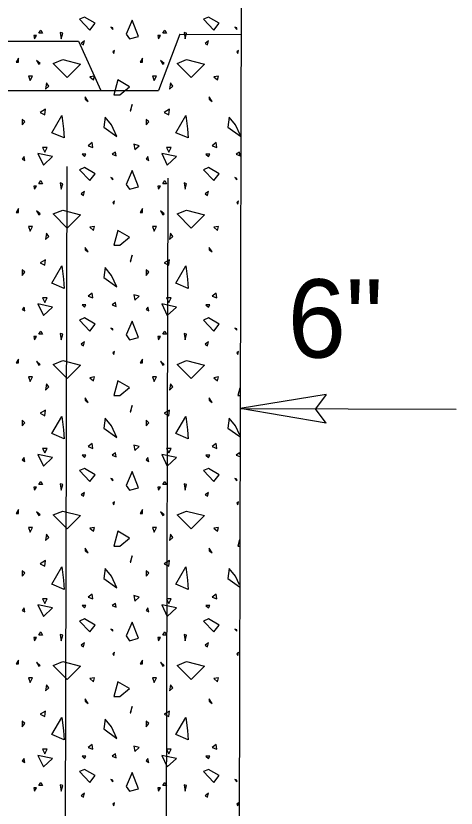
# Model space of a CAD drawing. Extents: x 9.6 to 16.8, y 2.2 to 12.2.
# Drawn here: x 15.979 to 16.317, y 7.596 to 8.202 of the extents above; entities that cross this region are included whole.
import ezdxf

# ---------------------------------------------------------------- set-up
doc = ezdxf.new("R2010")
doc.units = 0
for name, color, linetype in [('DETL-DIMS', 7, 'Continuous'), ('DETL-LINE', 7, 'Continuous'), ('DETL-NOTE', 7, 'Continuous'), ('DETL-PATT', 7, 'Continuous')]:
    doc.layers.add(name, color=color, linetype=linetype)

msp = doc.modelspace()

# ---------------------------------------------------------------- linework, layer by layer
at = {"layer": 'DETL-DIMS'}
for p, q in [((16.21722, 7.91235), (16.15129, 7.90149)), ((16.21722, 7.91235), (16.20894, 7.90137)), ((16.15129, 7.90149), (16.31678, 7.90118)), ((16.21714, 7.89039), (16.15129, 7.90149)), ((16.21714, 7.89039), (16.20894, 7.90137))]:
    msp.add_line(p, q, dxfattribs=at)
at = {"layer": 'DETL-LINE'}
for p, q in [((16.15333, 8.69231), (16.1489, 6.99)), ((14.99573, 8.18549), (16.02733, 8.18278)), ((16.1051, 8.18824), (16.08859, 8.14506)), ((16.1051, 8.18824), (16.15204, 8.18808)), ((16.02733, 8.18278), (16.04459, 8.14518)), ((14.97361, 8.14518), (16.04459, 8.14518)), ((16.04459, 8.14518), (16.08859, 8.14506)), ((16.01859, 8.08698), (16.01596, 7.08408)), ((16.09588, 8.07784), (16.0931, 7.02231))]:
    msp.add_line(p, q, dxfattribs=at)
at = {"layer": 'DETL-PATT'}
for points in [[(16.02827, 8.19961), (16.03604, 8.19129), (16.04027, 8.19651), (16.03192, 8.20133)], [(16.06639, 8.18467), (16.07345, 8.18651), (16.06863, 8.1989), (16.064, 8.18831)], [(16.12329, 8.19961), (16.13106, 8.19129), (16.13529, 8.19651), (16.12694, 8.20133)], [(15.99863, 8.19129), (15.99988, 8.1889), (15.99694, 8.1889)], [(16.0538, 8.19298), (16.05212, 8.19357), (16.0538, 8.19184)], [(16.09365, 8.19129), (16.0949, 8.1889), (16.09192, 8.1889)], [(16.14882, 8.19298), (16.14714, 8.19357), (16.14882, 8.19184)], [(15.99325, 8.18706), (15.9938, 8.18467), (15.9951, 8.18706)], [(16.01345, 8.18945), (16.01416, 8.18467), (16.01529, 8.1889)], [(16.08827, 8.18706), (16.08882, 8.18467), (16.09012, 8.18706)], [(16.10847, 8.18945), (16.10918, 8.18467), (16.11027, 8.1889)], [(16.02953, 8.18114), (16.03122, 8.18), (16.03192, 8.18298)], [(16.12455, 8.18114), (16.12624, 8.18), (16.12694, 8.18298)], [(16.0551, 8.17576), (16.0538, 8.17463), (16.05451, 8.17337)], [(16.15012, 8.17576), (16.14882, 8.17463), (16.14953, 8.17337)], [(15.98141, 8.16984), (15.97969, 8.16686), (15.98141, 8.16686)], [(15.99694, 8.16518), (15.99804, 8.16573), (15.9951, 8.16816)], [(16.01529, 8.16871), (16.02898, 8.16518), (16.01882, 8.15502), (16.00808, 8.16573)], [(16.07639, 8.16984), (16.07471, 8.16686), (16.07639, 8.16686)], [(16.09192, 8.16518), (16.09306, 8.16573), (16.09012, 8.16816)], [(16.11027, 8.16871), (16.124, 8.16518), (16.1138, 8.15502), (16.1031, 8.16573)], [(15.98918, 8.15616), (15.99027, 8.15263), (15.99212, 8.15616)], [(16.03604, 8.15557), (16.03898, 8.15318), (16.03957, 8.15616)], [(16.05918, 8.14188), (16.06639, 8.14796), (16.05749, 8.15318), (16.05451, 8.14188)], [(16.08416, 8.15616), (16.08529, 8.15263), (16.08714, 8.15616)], [(16.13106, 8.15557), (16.134, 8.15318), (16.13459, 8.15616)], [(16.00286, 8.1509), (16.00216, 8.14612), (16.00455, 8.14851)], [(16.09788, 8.1509), (16.09718, 8.14612), (16.09957, 8.14851)], [(16.03251, 8.1402), (16.03251, 8.13835), (16.0349, 8.13667)], [(16.12753, 8.1402), (16.12753, 8.13835), (16.12992, 8.13667)], [(15.99804, 8.12831), (16.00157, 8.12651), (16.00216, 8.13075)], [(16.06694, 8.12945), (16.06753, 8.12945), (16.06863, 8.13427)], [(16.09306, 8.12831), (16.09659, 8.12651), (16.09718, 8.13075)], [(15.98435, 8.12298), (15.98435, 8.11875), (15.9862, 8.12114)], [(16.01584, 8.11576), (16.01639, 8.10871), (16.00694, 8.11278), (16.01471, 8.12592)], [(16.04788, 8.12467), (16.04675, 8.11702), (16.05678, 8.10984), (16.05271, 8.11875)], [(16.07937, 8.12298), (16.07937, 8.11875), (16.08122, 8.12114)], [(16.11086, 8.11576), (16.11141, 8.10871), (16.10196, 8.11278), (16.10973, 8.12592)], [(16.03788, 8.10518), (16.0349, 8.10278), (16.03843, 8.10149)], [(16.13286, 8.10518), (16.12992, 8.10278), (16.13345, 8.10149)], [(15.99988, 8.10149), (16.00157, 8.09796), (16.00341, 8.10149)], [(16.06992, 8.10392), (16.07047, 8.0998), (16.074, 8.10278)], [(16.0949, 8.10149), (16.09659, 8.09796), (16.09843, 8.10149)], [(15.98435, 8.09263), (15.9862, 8.09149), (15.98565, 8.09443)], [(15.99624, 8.09686), (16.00047, 8.08796), (16.00753, 8.09443)], [(16.03012, 8.09627), (16.03192, 8.09443), (16.03306, 8.09627)], [(16.05325, 8.09627), (16.05624, 8.09502), (16.05565, 8.09796)], [(16.07937, 8.09263), (16.08122, 8.09149), (16.08063, 8.09443)], [(16.09122, 8.09686), (16.09545, 8.08796), (16.10251, 8.09443)], [(16.1251, 8.09627), (16.12694, 8.09443), (16.12808, 8.09627)], [(16.14827, 8.09627), (16.15122, 8.09502), (16.15067, 8.09796)], [(16.02827, 8.08443), (16.03604, 8.07608), (16.04027, 8.08133), (16.03192, 8.08612)], [(16.06639, 8.06945), (16.07345, 8.07129), (16.06863, 8.08373), (16.064, 8.07314)], [(16.12329, 8.08443), (16.13106, 8.07608), (16.13529, 8.08133), (16.12694, 8.08612)], [(15.99863, 8.07608), (15.99988, 8.07369), (15.99694, 8.07369)], [(16.01345, 8.07427), (16.01416, 8.06945), (16.01529, 8.07369)], [(16.0538, 8.0778), (16.05212, 8.07835), (16.0538, 8.07667)], [(16.09365, 8.07608), (16.0949, 8.07369), (16.09192, 8.07369)], [(16.10847, 8.07427), (16.10918, 8.06945), (16.11027, 8.07369)], [(16.14882, 8.0778), (16.14714, 8.07835), (16.14882, 8.07667)], [(15.99325, 8.07184), (15.9938, 8.06945), (15.9951, 8.07184)], [(16.08827, 8.07184), (16.08882, 8.06945), (16.09012, 8.07184)], [(16.02953, 8.06592), (16.03122, 8.06478), (16.03192, 8.06776)], [(16.12455, 8.06592), (16.12624, 8.06478), (16.12694, 8.06776)], [(16.0551, 8.06055), (16.0538, 8.05945), (16.05451, 8.05816)], [(16.15012, 8.06055), (16.14882, 8.05945), (16.14953, 8.05816)], [(15.98141, 8.05463), (15.97969, 8.05169), (15.98141, 8.05169)], [(15.99694, 8.04996), (15.99804, 8.05055), (15.9951, 8.05294)], [(16.01529, 8.05349), (16.02898, 8.04996), (16.01882, 8.0398), (16.00808, 8.05055)], [(16.07639, 8.05463), (16.07471, 8.05169), (16.07639, 8.05169)], [(16.09192, 8.04996), (16.09306, 8.05055), (16.09012, 8.05294)], [(16.11027, 8.05349), (16.124, 8.04996), (16.1138, 8.0398), (16.1031, 8.05055)], [(15.98918, 8.04094), (15.99027, 8.03741), (15.99212, 8.04094)], [(16.03604, 8.04039), (16.03898, 8.03796), (16.03957, 8.04094)], [(16.05918, 8.02667), (16.06639, 8.03275), (16.05749, 8.03796), (16.05451, 8.02667)], [(16.08416, 8.04094), (16.08529, 8.03741), (16.08714, 8.04094)], [(16.13106, 8.04039), (16.134, 8.03796), (16.13459, 8.04094)], [(16.00286, 8.03573), (16.00216, 8.0309), (16.00455, 8.03333)], [(16.09788, 8.03573), (16.09718, 8.0309), (16.09957, 8.03333)], [(16.03251, 8.02498), (16.03251, 8.02314), (16.0349, 8.02145)], [(16.12753, 8.02498), (16.12753, 8.02314), (16.12992, 8.02145)], [(15.99804, 8.01314), (16.00157, 8.01129), (16.00216, 8.01553)], [(16.06694, 8.01427), (16.06753, 8.01427), (16.06863, 8.01906)], [(16.09306, 8.01314), (16.09659, 8.01129), (16.09718, 8.01553)], [(15.98435, 8.00776), (15.98435, 8.00353), (15.9862, 8.00592)], [(16.01584, 8.00055), (16.01639, 7.99349), (16.00694, 7.99761), (16.01471, 8.01075)], [(16.04788, 8.00945), (16.04675, 8.00184), (16.05678, 7.99463), (16.05271, 8.00353)], [(16.07937, 8.00776), (16.07937, 8.00353), (16.08122, 8.00592)], [(16.11086, 8.00055), (16.11141, 7.99349), (16.10196, 7.99761), (16.10973, 8.01075)], [(16.03788, 7.98996), (16.0349, 7.98757), (16.03843, 7.98631)], [(16.13286, 7.98996), (16.12992, 7.98757), (16.13345, 7.98631)], [(15.99988, 7.98631), (16.00157, 7.98278), (16.00341, 7.98631)], [(16.06992, 7.98871), (16.07047, 7.98463), (16.074, 7.98757)], [(16.0949, 7.98631), (16.09659, 7.98278), (16.09843, 7.98631)], [(15.98435, 7.97741), (15.9862, 7.97627), (15.98565, 7.97925)], [(15.99624, 7.98165), (16.00047, 7.97275), (16.00753, 7.97925)], [(16.03012, 7.9811), (16.03192, 7.97925), (16.03306, 7.9811)], [(16.05325, 7.9811), (16.05624, 7.9798), (16.05565, 7.98278)], [(16.07937, 7.97741), (16.08122, 7.97627), (16.08063, 7.97925)], [(16.09122, 7.98165), (16.09545, 7.97275), (16.10251, 7.97925)], [(16.1251, 7.9811), (16.12694, 7.97925), (16.12808, 7.9811)], [(16.02827, 7.96922), (16.03604, 7.9609), (16.04027, 7.96612), (16.03192, 7.9709)], [(16.06639, 7.95427), (16.07345, 7.95608), (16.06863, 7.96851), (16.064, 7.95792)], [(16.12329, 7.96922), (16.13106, 7.9609), (16.13529, 7.96612), (16.12694, 7.9709)], [(15.99863, 7.9609), (15.99988, 7.95851), (15.99694, 7.95851)], [(16.01345, 7.95906), (16.01416, 7.95427), (16.01529, 7.95851)], [(16.0538, 7.96259), (16.05212, 7.96314), (16.0538, 7.96145)], [(16.09365, 7.9609), (16.0949, 7.95851), (16.09192, 7.95851)], [(16.10847, 7.95906), (16.10918, 7.95427), (16.11027, 7.95851)], [(16.14882, 7.96259), (16.14714, 7.96314), (16.14882, 7.96145)], [(15.99325, 7.95667), (15.9938, 7.95427), (15.9951, 7.95667)], [(16.08827, 7.95667), (16.08882, 7.95427), (16.09012, 7.95667)], [(16.02953, 7.95075), (16.03122, 7.94961), (16.03192, 7.95255)], [(16.12455, 7.95075), (16.12624, 7.94961), (16.12694, 7.95255)], [(16.0551, 7.94537), (16.0538, 7.94424), (16.05451, 7.94298)], [(16.15012, 7.94537), (16.14882, 7.94424), (16.14953, 7.94298)], [(15.98141, 7.93945), (15.97969, 7.93647), (15.98141, 7.93647)], [(15.99694, 7.93478), (15.99804, 7.93533), (15.9951, 7.93773)], [(16.01529, 7.93831), (16.02898, 7.93478), (16.01882, 7.92463), (16.00808, 7.93533)], [(16.07639, 7.93945), (16.07471, 7.93647), (16.07639, 7.93647)], [(16.09192, 7.93478), (16.09306, 7.93533), (16.09012, 7.93773)], [(16.11027, 7.93831), (16.124, 7.93478), (16.1138, 7.92463), (16.1031, 7.93533)], [(15.98918, 7.92573), (15.99027, 7.9222), (15.99212, 7.92573)], [(16.03604, 7.92518), (16.03898, 7.92278), (16.03957, 7.92573)], [(16.05918, 7.91149), (16.06639, 7.91757), (16.05749, 7.92278), (16.05451, 7.91149)], [(16.08416, 7.92573), (16.08529, 7.9222), (16.08714, 7.92573)], [(16.13106, 7.92518), (16.134, 7.92278), (16.13459, 7.92573)], [(16.00286, 7.92051), (16.00216, 7.91573), (16.00455, 7.91812)], [(16.09788, 7.92051), (16.09718, 7.91573), (16.09957, 7.91812)], [(16.03251, 7.9098), (16.03251, 7.90796), (16.0349, 7.90627)], [(16.12753, 7.9098), (16.12753, 7.90796), (16.12992, 7.90627)], [(15.99804, 7.89792), (16.00157, 7.89608), (16.00216, 7.90031)], [(16.06694, 7.89906), (16.06753, 7.89906), (16.06863, 7.90384)], [(16.09306, 7.89792), (16.09659, 7.89608), (16.09718, 7.90031)], [(15.98435, 7.89255), (15.98435, 7.88831), (15.9862, 7.89075)], [(16.01584, 7.88537), (16.01639, 7.87831), (16.00694, 7.88239), (16.01471, 7.89553)], [(16.04788, 7.89427), (16.04675, 7.88663), (16.05678, 7.87945), (16.05271, 7.88831)], [(16.07937, 7.89255), (16.07937, 7.88831), (16.08122, 7.89075)], [(16.11086, 7.88537), (16.11141, 7.87831), (16.10196, 7.88239), (16.10973, 7.89553)], [(16.03788, 7.87478), (16.0349, 7.87239), (16.03843, 7.8711)], [(16.13286, 7.87478), (16.12992, 7.87239), (16.13345, 7.8711)], [(15.99988, 7.8711), (16.00157, 7.86757), (16.00341, 7.8711)], [(16.06992, 7.87349), (16.07047, 7.86941), (16.074, 7.87239)], [(16.0949, 7.8711), (16.09659, 7.86757), (16.09843, 7.8711)], [(15.98435, 7.8622), (15.9862, 7.8611), (15.98565, 7.86404)], [(15.99624, 7.86643), (16.00047, 7.85757), (16.00753, 7.86404)], [(16.03012, 7.86588), (16.03192, 7.86404), (16.03306, 7.86588)], [(16.05325, 7.86588), (16.05624, 7.86463), (16.05565, 7.86757)], [(16.07937, 7.8622), (16.08122, 7.8611), (16.08063, 7.86404)], [(16.09122, 7.86643), (16.09545, 7.85757), (16.10251, 7.86404)], [(16.1251, 7.86588), (16.12694, 7.86404), (16.12808, 7.86588)], [(16.02827, 7.85404), (16.03604, 7.84569), (16.04027, 7.8509), (16.03192, 7.85573)], [(16.06639, 7.83906), (16.07345, 7.8409), (16.06863, 7.85333), (16.064, 7.84275)], [(16.12329, 7.85404), (16.13106, 7.84569), (16.13529, 7.8509), (16.12694, 7.85573)], [(15.99863, 7.84569), (15.99988, 7.84329), (15.99694, 7.84329)], [(16.01345, 7.84384), (16.01416, 7.83906), (16.01529, 7.84329)], [(16.0538, 7.84737), (16.05212, 7.84796), (16.0538, 7.84627)], [(16.09365, 7.84569), (16.0949, 7.84329), (16.09192, 7.84329)], [(16.10847, 7.84384), (16.10918, 7.83906), (16.11027, 7.84329)], [(16.14882, 7.84737), (16.14714, 7.84796), (16.14882, 7.84627)], [(15.99325, 7.84145), (15.9938, 7.83906), (15.9951, 7.84145)], [(16.08827, 7.84145), (16.08882, 7.83906), (16.09012, 7.84145)], [(16.02953, 7.83553), (16.03122, 7.83439), (16.03192, 7.83737)], [(16.12455, 7.83553), (16.12624, 7.83439), (16.12694, 7.83737)], [(16.0551, 7.83016), (16.0538, 7.82902), (16.05451, 7.82776)], [(16.15012, 7.83016), (16.14882, 7.82902), (16.14953, 7.82776)], [(15.98141, 7.82424), (15.97969, 7.82125), (15.98141, 7.82125)], [(15.99694, 7.81957), (15.99804, 7.82016), (15.9951, 7.82255)], [(16.01529, 7.8231), (16.02898, 7.81957), (16.01882, 7.80941), (16.00808, 7.82016)], [(16.07639, 7.82424), (16.07471, 7.82125), (16.07639, 7.82125)], [(16.09192, 7.81957), (16.09306, 7.82016), (16.09012, 7.82255)], [(16.11027, 7.8231), (16.124, 7.81957), (16.1138, 7.80941), (16.1031, 7.82016)], [(15.98918, 7.81055), (15.99027, 7.80702), (15.99212, 7.81055)], [(16.03604, 7.80996), (16.03898, 7.80757), (16.03957, 7.81055)], [(16.05918, 7.79627), (16.06639, 7.80235), (16.05749, 7.80757), (16.05451, 7.79627)], [(16.08416, 7.81055), (16.08529, 7.80702), (16.08714, 7.81055)], [(16.13106, 7.80996), (16.134, 7.80757), (16.13459, 7.81055)], [(16.00286, 7.80533), (16.00216, 7.80051), (16.00455, 7.8029)], [(16.09788, 7.80533), (16.09718, 7.80051), (16.09957, 7.8029)], [(16.03251, 7.79459), (16.03251, 7.79275), (16.0349, 7.79106)], [(16.12753, 7.79459), (16.12753, 7.79275), (16.12992, 7.79106)], [(15.99804, 7.78275), (16.00157, 7.7809), (16.00216, 7.78514)], [(16.06694, 7.78384), (16.06753, 7.78384), (16.06863, 7.78867)], [(16.09306, 7.78275), (16.09659, 7.7809), (16.09718, 7.78514)], [(15.98435, 7.77737), (15.98435, 7.77314), (15.9862, 7.77553)], [(16.01584, 7.77016), (16.01639, 7.7631), (16.00694, 7.76722), (16.01471, 7.78031)], [(16.04788, 7.77906), (16.04675, 7.77145), (16.05678, 7.76424), (16.05271, 7.77314)], [(16.07937, 7.77737), (16.07937, 7.77314), (16.08122, 7.77553)], [(16.11086, 7.77016), (16.11141, 7.7631), (16.10196, 7.76722), (16.10973, 7.78031)], [(16.03788, 7.75957), (16.0349, 7.75718), (16.03843, 7.75592)], [(16.13286, 7.75957), (16.12992, 7.75718), (16.13345, 7.75592)], [(15.99988, 7.75592), (16.00157, 7.75239), (16.00341, 7.75592)], [(16.06992, 7.75831), (16.07047, 7.7542), (16.074, 7.75718)], [(16.0949, 7.75592), (16.09659, 7.75239), (16.09843, 7.75592)], [(15.98435, 7.74702), (15.9862, 7.74588), (15.98565, 7.74886)], [(15.99624, 7.75125), (16.00047, 7.74235), (16.00753, 7.74886)], [(16.03012, 7.75067), (16.03192, 7.74886), (16.03306, 7.75067)], [(16.05325, 7.75067), (16.05624, 7.74941), (16.05565, 7.75239)], [(16.07937, 7.74702), (16.08122, 7.74588), (16.08063, 7.74886)], [(16.09122, 7.75125), (16.09545, 7.74235), (16.10251, 7.74886)], [(16.1251, 7.75067), (16.12694, 7.74886), (16.12808, 7.75067)], [(16.02827, 7.73882), (16.03604, 7.73051), (16.04027, 7.73573), (16.03192, 7.74051)], [(16.06639, 7.72384), (16.07345, 7.72569), (16.06863, 7.73812), (16.064, 7.72753)], [(16.12329, 7.73882), (16.13106, 7.73051), (16.13529, 7.73573), (16.12694, 7.74051)], [(15.99863, 7.73051), (15.99988, 7.72808), (15.99694, 7.72808)], [(16.01345, 7.72867), (16.01416, 7.72384), (16.01529, 7.72808)], [(16.0538, 7.7322), (16.05212, 7.73275), (16.0538, 7.73106)], [(16.09365, 7.73051), (16.0949, 7.72808), (16.09192, 7.72808)], [(16.10847, 7.72867), (16.10918, 7.72384), (16.11027, 7.72808)], [(16.14882, 7.7322), (16.14714, 7.73275), (16.14882, 7.73106)], [(15.99325, 7.72627), (15.9938, 7.72384), (15.9951, 7.72627)], [(16.08827, 7.72627), (16.08882, 7.72384), (16.09012, 7.72627)], [(16.02953, 7.72031), (16.03122, 7.71922), (16.03192, 7.72216)], [(16.12455, 7.72031), (16.12624, 7.71922), (16.12694, 7.72216)], [(16.0551, 7.71498), (16.0538, 7.71384), (16.05451, 7.71255)], [(16.15012, 7.71498), (16.14882, 7.71384), (16.14953, 7.71255)], [(15.98141, 7.70902), (15.97969, 7.70608), (15.98141, 7.70608)], [(15.99694, 7.70439), (15.99804, 7.70494), (15.9951, 7.70733)], [(16.01529, 7.70792), (16.02898, 7.70439), (16.01882, 7.6942), (16.00808, 7.70494)], [(16.07639, 7.70902), (16.07471, 7.70608), (16.07639, 7.70608)], [(16.09192, 7.70439), (16.09306, 7.70494), (16.09012, 7.70733)], [(16.11027, 7.70792), (16.124, 7.70439), (16.1138, 7.6942), (16.1031, 7.70494)], [(15.98918, 7.69533), (15.99027, 7.6918), (15.99212, 7.69533)], [(16.03604, 7.69478), (16.03898, 7.69239), (16.03957, 7.69533)], [(16.05918, 7.6811), (16.06639, 7.68714), (16.05749, 7.69239), (16.05451, 7.6811)], [(16.08416, 7.69533), (16.08529, 7.6918), (16.08714, 7.69533)], [(16.13106, 7.69478), (16.134, 7.69239), (16.13459, 7.69533)], [(16.00286, 7.69012), (16.00216, 7.68533), (16.00455, 7.68773)], [(16.09788, 7.69012), (16.09718, 7.68533), (16.09957, 7.68773)], [(16.03251, 7.67937), (16.03251, 7.67757), (16.0349, 7.67584)], [(16.12753, 7.67937), (16.12753, 7.67757), (16.12992, 7.67584)], [(15.99804, 7.66753), (16.00157, 7.66569), (16.00216, 7.66992)], [(16.06694, 7.66867), (16.06753, 7.66867), (16.06863, 7.67345)], [(16.09306, 7.66753), (16.09659, 7.66569), (16.09718, 7.66992)], [(15.98435, 7.66216), (15.98435, 7.65792), (15.9862, 7.66031)], [(16.01584, 7.65498), (16.01639, 7.64792), (16.00694, 7.652), (16.01471, 7.66514)], [(16.04788, 7.66384), (16.04675, 7.65624), (16.05678, 7.64902), (16.05271, 7.65792)], [(16.07937, 7.66216), (16.07937, 7.65792), (16.08122, 7.66031)], [(16.11086, 7.65498), (16.11141, 7.64792), (16.10196, 7.652), (16.10973, 7.66514)], [(16.03788, 7.64439), (16.0349, 7.64196), (16.03843, 7.64071)], [(16.13286, 7.64439), (16.12992, 7.64196), (16.13345, 7.64071)], [(15.99988, 7.64071), (16.00157, 7.63718), (16.00341, 7.64071)], [(16.06992, 7.6431), (16.07047, 7.63902), (16.074, 7.64196)], [(16.0949, 7.64071), (16.09659, 7.63718), (16.09843, 7.64071)], [(15.98435, 7.6318), (15.9862, 7.63067), (15.98565, 7.63365)], [(15.99624, 7.63604), (16.00047, 7.62714), (16.00753, 7.63365)], [(16.03012, 7.63549), (16.03192, 7.63365), (16.03306, 7.63549)], [(16.05325, 7.63549), (16.05624, 7.6342), (16.05565, 7.63718)], [(16.07937, 7.6318), (16.08122, 7.63067), (16.08063, 7.63365)], [(16.09122, 7.63604), (16.09545, 7.62714), (16.10251, 7.63365)], [(16.1251, 7.63549), (16.12694, 7.63365), (16.12808, 7.63549)], [(16.02827, 7.62361), (16.03604, 7.61529), (16.04027, 7.62051), (16.03192, 7.62533)], [(16.12329, 7.62361), (16.13106, 7.61529), (16.13529, 7.62051), (16.12694, 7.62533)], [(16.06639, 7.60867), (16.07345, 7.61051), (16.06863, 7.6229), (16.064, 7.61231)], [(15.99863, 7.61529), (15.99988, 7.6129), (15.99694, 7.6129)], [(16.01345, 7.61345), (16.01416, 7.60867), (16.01529, 7.6129)], [(16.0538, 7.61698), (16.05212, 7.61757), (16.0538, 7.61584)], [(16.09365, 7.61529), (16.0949, 7.6129), (16.09192, 7.6129)], [(16.10847, 7.61345), (16.10918, 7.60867), (16.11027, 7.6129)], [(16.14882, 7.61698), (16.14714, 7.61757), (16.14882, 7.61584)], [(15.99325, 7.61106), (15.9938, 7.60867), (15.9951, 7.61106)], [(16.08827, 7.61106), (16.08882, 7.60867), (16.09012, 7.61106)], [(16.02953, 7.60514), (16.03122, 7.604), (16.03192, 7.60698)], [(16.12455, 7.60514), (16.12624, 7.604), (16.12694, 7.60698)], [(16.0551, 7.59976), (16.0538, 7.59863), (16.05451, 7.59737)], [(16.15012, 7.59976), (16.14882, 7.59863), (16.14953, 7.59737)]]:
    msp.add_lwpolyline(points, close=True, dxfattribs=at)
for points in [[(16.15145, 8.11055), (16.14769, 8.11875), (16.1429, 8.12467), (16.14176, 8.11702), (16.15145, 8.11008)], [(16.15102, 7.91718), (16.14953, 7.91149), (16.15102, 7.91149)], [(16.15094, 7.88129), (16.14769, 7.88831), (16.1429, 7.89427), (16.14176, 7.88663), (16.15094, 7.88008)], [(16.1509, 7.86627), (16.15067, 7.86757), (16.14827, 7.86588), (16.1509, 7.86475)], [(16.15075, 7.80094), (16.14953, 7.79627), (16.15075, 7.79627)], [(16.15067, 7.76667), (16.14769, 7.77314), (16.1429, 7.77906), (16.14176, 7.77145), (16.15067, 7.76506)]]:
    msp.add_lwpolyline(points, dxfattribs=at)

# ---------------------------------------------------------------- texts
at = {"layer": 'DETL-NOTE'}
msp.add_text('6"', height=0.06, dxfattribs=at).set_placement((16.18769, 7.94055))

doc.saveas('drawing.dxf')
